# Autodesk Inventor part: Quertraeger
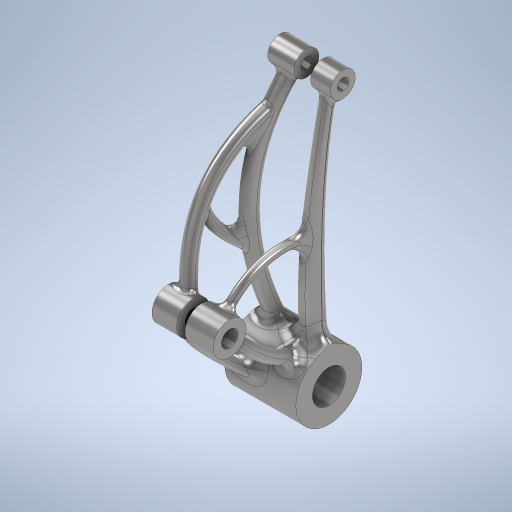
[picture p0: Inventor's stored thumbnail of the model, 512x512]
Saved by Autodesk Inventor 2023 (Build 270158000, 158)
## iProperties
Company: none
Created: 2023-01
Part Number: Quertraeger
Material: Stahl, Guss
Description: CATIA V5 STEP Exchange
Document SubType Name: Modeling
Designer: patri
Authority: none
Density: 7.85 g/cm^3
Appearance: Halbpoliert
Mass: 650.703 g
Surface Area: 288.755 cm^2
Volume: 82.8922 cm^3
Sending System: CATIA V5 STEP AP203
Preprocessor: CATIA Version 5 Release 19 GA (IN-10)
Title: X:\_BBS Brinkstraße\CAD\Quertraeger_Patricia\Quertraeger.stp
Author: none
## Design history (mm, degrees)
feature "Hauptkörper"
node "Volumenkörper1"
